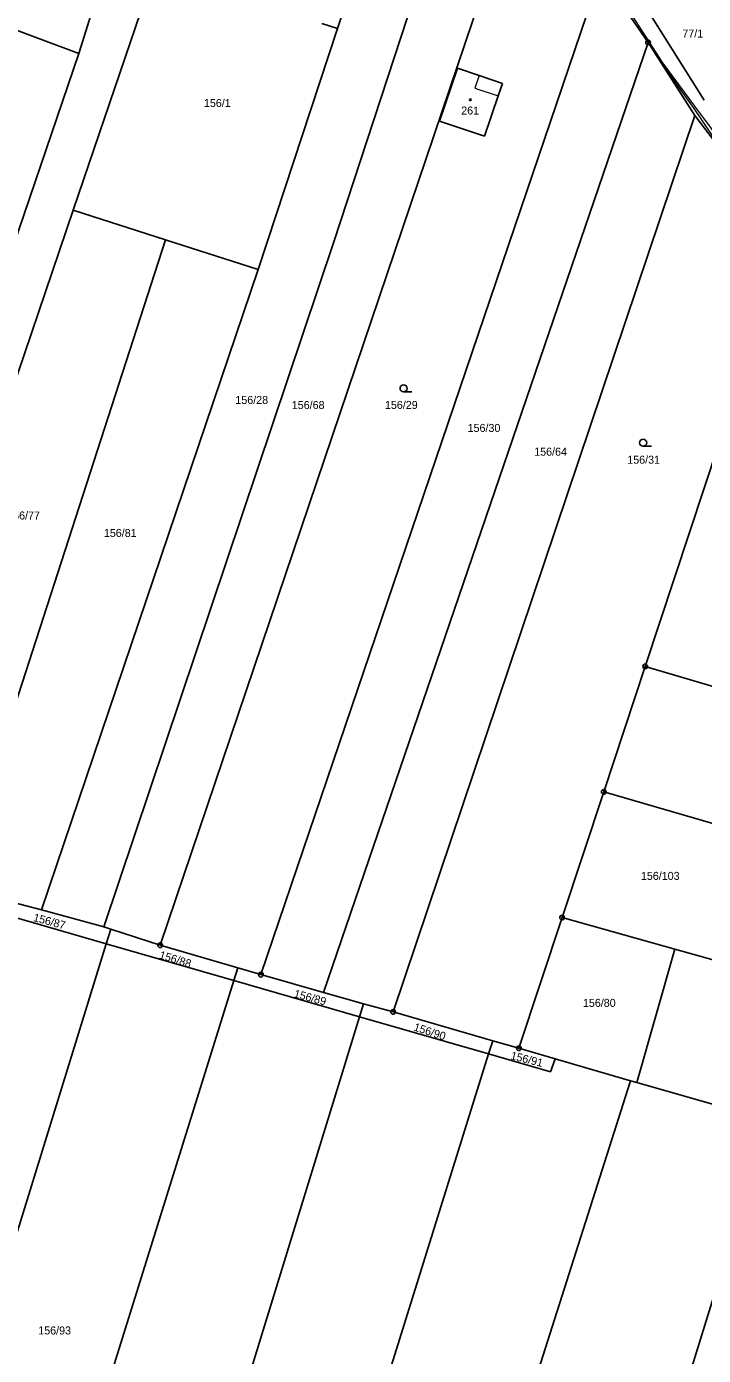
# Model space of a CAD drawing. Extents: x -694609 to -690140, y -1033292 to -1029794.
# Drawn here: x -693359.6 to -693215.9, y -1031527.4 to -1031245.2 of the extents above; entities that cross this region are included whole.
import ezdxf
from ezdxf.enums import TextEntityAlignment as Align

# ---------------------------------------------------------------- set-up
doc = ezdxf.new("R2010")
doc.units = 0
doc.header["$LTSCALE"] = 0.68
for name, color, linetype, lineweight in [('1', 7, 'Continuous', 25), ('13', 7, 'Continuous', 13), ('3', 7, 'Continuous', 25), ('4', 7, 'Continuous', 13), ('5', 7, 'Continuous', 25), ('8', 7, 'Continuous', 25)]:
    doc.layers.add(name, color=color, linetype=linetype, lineweight=lineweight)
doc.layers.add('2', color=7, linetype='Continuous')

msp = doc.modelspace()

# ---------------------------------------------------------------- linework, layer by layer
at = {"layer": '1'}
for p, q in [((-693255.38, -1031215.82), (-693331.24, -1031440.29)), ((-693331.34, -1031230.32), (-693349.69, -1031284.17)), ((-693234.03, -1031231.76), (-693215.77, -1031260.84)), ((-693237.69, -1031233.95), (-693309.85, -1031446.55)), ((-693385.3, -1031237.2), (-693348.5, -1031250.94)), ((-693294.34, -1031290.95), (-693276.73, -1031237.11)), ((-693293.58, -1031245.65), (-693290.7, -1031236.94)), ((-693345.22, -1031240.5), (-693348.5, -1031250.94)), ((-693293.58, -1031245.65), (-693296.9, -1031244.56)), ((-693293.58, -1031245.65), (-693310.45, -1031296.82)), ((-693227.67, -1031248.57), (-693296.52, -1031450.36)), ((-693348.5, -1031250.94), (-693383.8, -1031354.59)), ((-693268.15, -1031254.06), (-693271.94, -1031265.29)), ((-693268.15, -1031254.06), (-693263.55, -1031255.61)), ((-693263.55, -1031255.61), (-693258.58, -1031257.28)), ((-693258.58, -1031257.28), (-693259.48, -1031259.94)), ((-693259.48, -1031259.94), (-693262.37, -1031268.52)), ((-693281.78, -1031454.45), (-693217.72, -1031264.13)), ((-693217.72, -1031264.13), (-693198.18, -1031289.92)), ((-693262.37, -1031268.52), (-693271.94, -1031265.29)), ((-693349.69, -1031284.17), (-693396.46, -1031422.25)), ((-693330.08, -1031290.49), (-693349.69, -1031284.17)), ((-693330.08, -1031290.49), (-693374.58, -1031428.04)), ((-693343.17, -1031436.39), (-693294.34, -1031290.95)), ((-693310.45, -1031296.82), (-693330.08, -1031290.49)), ((-693198.18, -1031289.92), (-693228.28, -1031381.08)), ((-693310.45, -1031296.82), (-693356.42, -1031432.78)), ((-693237.08, -1031407.73), (-693228.28, -1031381.08)), ((-693228.28, -1031381.08), (-693209.17, -1031386.78)), ((-693245.93, -1031434.44), (-693237.08, -1031407.73)), ((-693237.08, -1031407.73), (-693203.62, -1031417.48)), ((-693356.42, -1031432.78), (-693368.7, -1031429.57)), ((-693369.53, -1031432.24), (-693342.67, -1031439.99)), ((-693356.42, -1031432.78), (-693343.17, -1031436.39)), ((-693341.71, -1031436.87), (-693343.17, -1031436.39)), ((-693255.07, -1031462.19), (-693245.93, -1031434.44)), ((-693341.71, -1031436.87), (-693342.67, -1031439.99)), ((-693331.24, -1031440.29), (-693341.71, -1031436.87)), ((-693342.67, -1031439.99), (-693395.23, -1031610.15)), ((-693342.67, -1031439.99), (-693315.6, -1031447.79)), ((-693314.77, -1031445.11), (-693331.24, -1031440.29)), ((-693221.97, -1031441.13), (-693230.03, -1031469.43)), ((-693314.77, -1031445.11), (-693315.6, -1031447.79)), ((-693309.85, -1031446.55), (-693314.77, -1031445.11)), ((-693315.6, -1031447.79), (-693288.88, -1031455.5)), ((-693309.85, -1031446.55), (-693296.52, -1031450.36)), ((-693296.52, -1031450.36), (-693288.03, -1031452.72)), ((-693288.03, -1031452.72), (-693288.88, -1031455.5)), ((-693288.03, -1031452.72), (-693281.78, -1031454.45)), ((-693288.88, -1031455.5), (-693341.6, -1031626.81)), ((-693288.88, -1031455.5), (-693261.5, -1031463.39)), ((-693281.78, -1031454.45), (-693260.62, -1031460.58)), ((-693260.62, -1031460.58), (-693261.5, -1031463.39)), ((-693260.62, -1031460.58), (-693255.07, -1031462.19)), ((-693261.5, -1031463.39), (-693315.03, -1031635.06)), ((-693261.5, -1031463.39), (-693248.37, -1031467.18)), ((-693255.07, -1031462.19), (-693247.41, -1031464.4)), ((-693248.37, -1031467.18), (-693247.41, -1031464.4)), ((-693247.41, -1031464.4), (-693231.42, -1031469.1)), ((-693231.42, -1031469.1), (-693287, -1031643.81)), ((-693231.42, -1031469.1), (-693230.03, -1031469.43)), ((-693230.03, -1031469.43), (-693202.25, -1031477.47)), ((-693202.25, -1031477.47), (-693256.34, -1031653.33))]:
    msp.add_line(p, q, dxfattribs=at)
for points in [[(-693237.69, -1031233.95), (-693227.67, -1031248.57), (-693217.72, -1031264.13)], [(-693245.93, -1031434.44), (-693221.97, -1031441.13), (-693212.35, -1031443.81)], [(-693315.6, -1031447.79), (-693368.77, -1031618.37), (-693395.23, -1031610.15)]]:
    msp.add_lwpolyline(points, dxfattribs=at)
at = {"layer": '13'}
msp.add_lwpolyline([(-693200.24, -1031285.53), (-693217.75, -1031262.13), (-693224.52, -1031252.92), (-693230.99, -1031242.92), (-693236.58, -1031234.54), (-693237.06, -1031234.87), (-693227.67, -1031248.57), (-693224.82, -1031253.03), (-693217.95, -1031262.64), (-693210.63, -1031273.49)], close=True, dxfattribs=at)
at = {"layer": '3'}
for p, q in [((-693279.563, -1031322.8), (-693277.813, -1031322.8)), ((-693228.713, -1031334.34), (-693226.963, -1031334.34))]:
    msp.add_line(p, q, dxfattribs=at)
for centre in [(-693279.5629, -1031322.0498), (-693228.7129, -1031333.5898)]:
    msp.add_circle(centre, 0.75, dxfattribs=at)
at = {"layer": '4'}
for p, q in [((-693263.55, -1031255.61), (-693264.45, -1031258.27)), ((-693264.45, -1031258.27), (-693259.48, -1031259.94))]:
    msp.add_line(p, q, dxfattribs=at)
at = {"layer": '5'}
msp.add_circle((-693265.4068, -1031260.7592), 0.175, dxfattribs=at)
at = {"layer": '8'}
for centre, radius in [((-693227.67, -1031248.5699), 0.5), ((-693227.67, -1031248.5699), 0.0303), ((-693228.28, -1031381.0799), 0.5), ((-693228.28, -1031381.0799), 0.0303), ((-693237.08, -1031407.7299), 0.5), ((-693237.08, -1031407.7299), 0.0303), ((-693245.93, -1031434.4399), 0.5), ((-693245.93, -1031434.4399), 0.0303), ((-693331.24, -1031440.2899), 0.5), ((-693331.24, -1031440.2899), 0.0303), ((-693309.85, -1031446.5499), 0.5), ((-693309.85, -1031446.5499), 0.0303), ((-693281.78, -1031454.4499), 0.5), ((-693281.78, -1031454.4499), 0.0303), ((-693255.07, -1031462.1899), 0.5), ((-693255.07, -1031462.1899), 0.0303)]:
    msp.add_circle(centre, radius, dxfattribs=at)

# ---------------------------------------------------------------- texts
at = {"layer": '2'}
for s, p in [('77/1', (-693218.179, -1031247.545)), ('156/1', (-693319.09, -1031262.295)), ('261', (-693265.429, -1031263.895)), ('156/28', (-693311.79, -1031325.355)), ('156/68', (-693299.81, -1031326.435)), ('156/29', (-693280.04, -1031326.415)), ('156/30', (-693262.49, -1031331.295)), ('156/64', (-693248.36, -1031336.345)), ('156/31', (-693228.61, -1031338.045)), ('156/77', (-693360.21, -1031349.895)), ('156/81', (-693339.69, -1031353.605)), ('156/80', (-693238.02, -1031453.395)), ('156/93', (-693353.62, -1031522.955))]:
    msp.add_text(s, height=1.7, dxfattribs=at).set_placement(p, align=Align.CENTER)
msp.add_text('156/103', height=1.7, dxfattribs=at).set_placement((-693229.19, -1031426.425))
for s, rotation, p in [('156/87', 345, (-693354.928, -1031436.0501)), ('156/88', 343, (-693328.2375, -1031444.0942)), ('156/89', 345, (-693299.608, -1031452.2201)), ('156/90', 342, (-693274.2577, -1031459.4476)), ('156/91', 346, (-693253.5881, -1031465.3276))]:
    msp.add_text(s, height=1.7, rotation=rotation, dxfattribs=at).set_placement(p, align=Align.CENTER)

doc.saveas('drawing.dxf')
